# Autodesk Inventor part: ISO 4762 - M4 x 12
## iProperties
Comments: To add or edit properties for Autodesk Inventor files, use iProperties.
Created: 2004-08
Part Number: ISO 4762 - M4 x 12
Vendor: Autodesk Inc.
Document SubType Name: Modeling
Designer: John Blackburn
Material: Default
Description: Hexagon Socket Head Cap Screw
Standard: ISO 4762
Size Designation: M4 x 12
Alert: To add or edit properties for Autodesk Inventor files, use iProperties.
Control State: 0
Master: False
Checked Out: False
Shininess: 64.0
Length Units: 11269
Angle Units: 11279
Time Units: 11290
Mass Units: 11283
Length Display Precision: 3
Angle Display Precision: 2
Compacted: True
EGR: 1
Density: 0.0
Volumn: 0.0
Area: 0.0
PropertySet Name: Model Information
Author: John Blackburn
Revision Number: 8
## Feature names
1. Body [Revolution]
2. Slot [Extrusion]
3. Fillet1
4. Chamfer1
